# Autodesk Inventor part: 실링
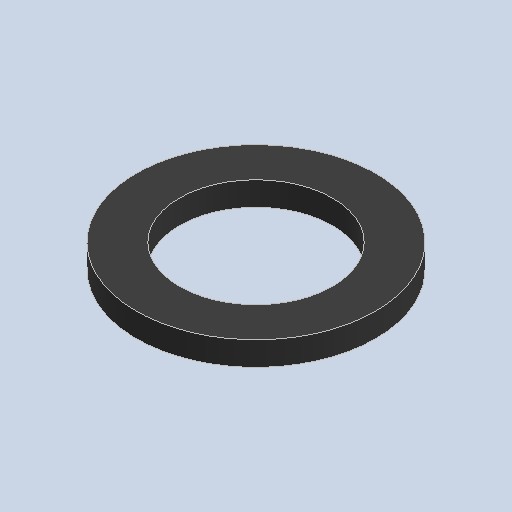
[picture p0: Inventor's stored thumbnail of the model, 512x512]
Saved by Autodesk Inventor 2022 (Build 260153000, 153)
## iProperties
Created: 2024-11
Part Number: 실링
Material: 고무
Document SubType Name: Modeling
Designer: PC-12
Density: 0.93 g/cm^3
Appearance: 기본값
Author: jhkim
Sending System: Autodesk Inventor 2025
Preprocessor: ST-DEVELOPER v20
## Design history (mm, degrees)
node "실링1"
node "솔리드2"
node "솔리드1"
